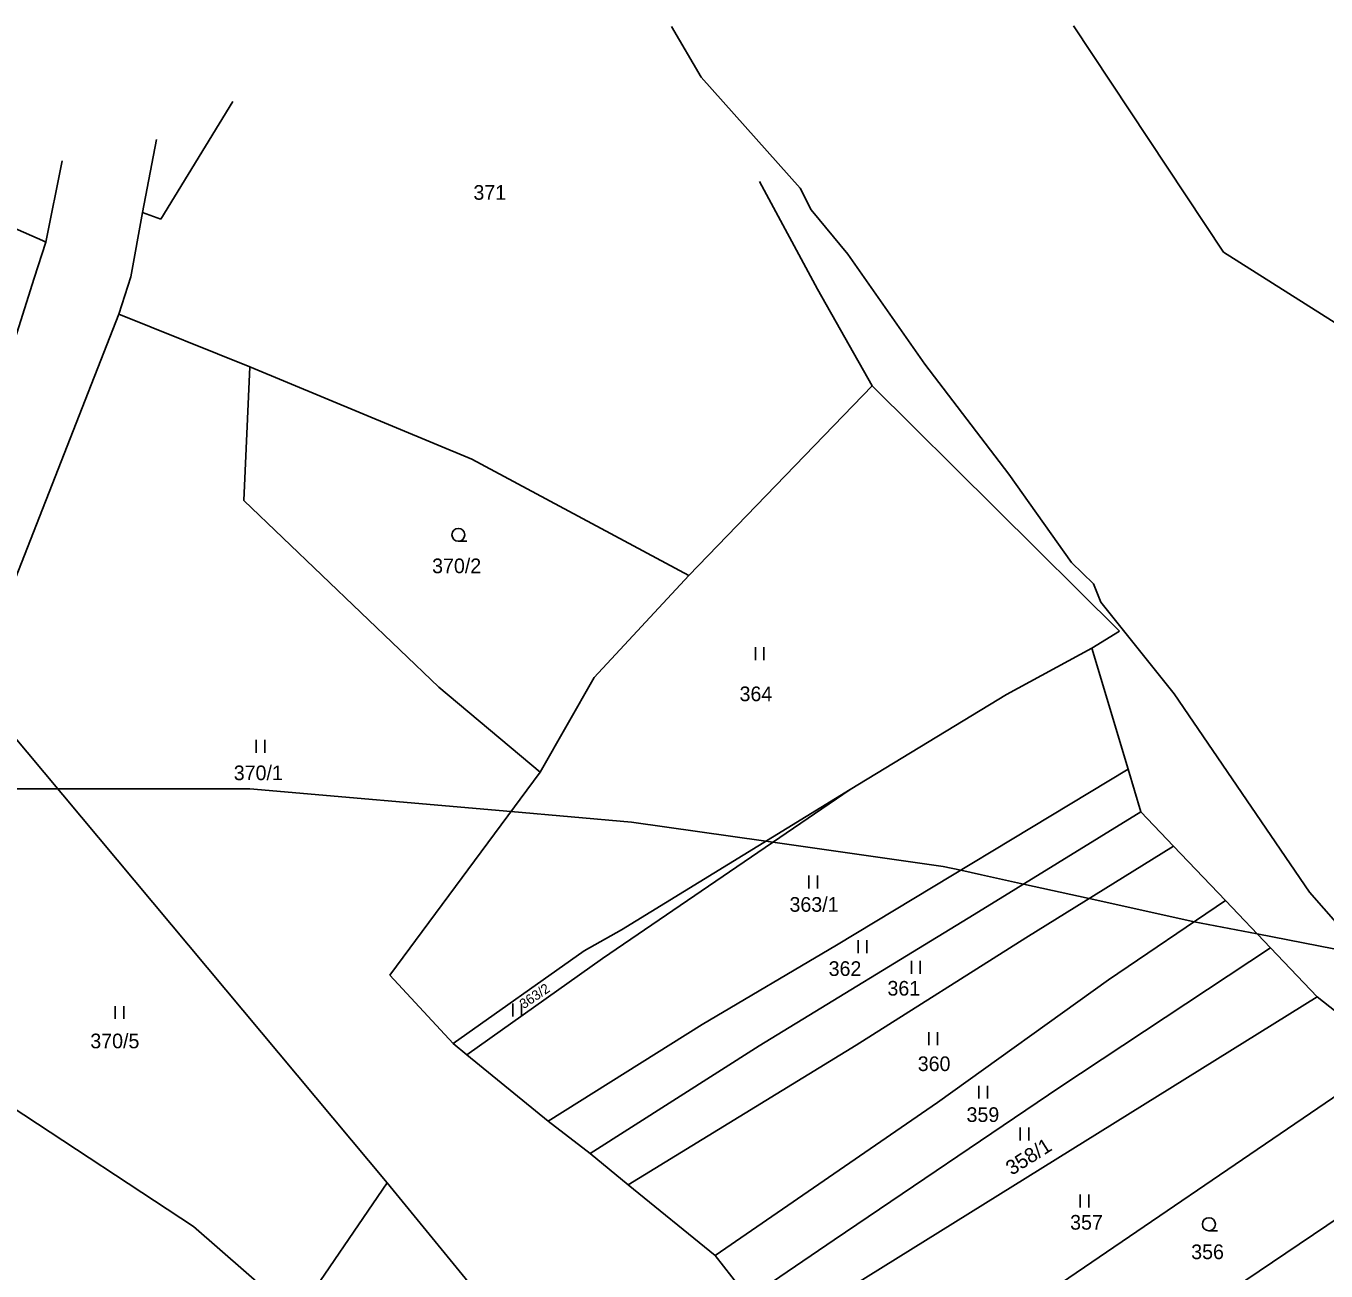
# Model space of a CAD drawing. Extents: x -749173 to -746119, y -1132678 to -1130338.
# Drawn here: x -747979.1 to -747828.3, y -1130840.9 to -1130696.6 of the extents above; entities that cross this region are included whole.
import ezdxf

# ---------------------------------------------------------------- set-up
doc = ezdxf.new("R2010")
doc.units = 0
for name, color, linetype in [('Vrstva 1', 7, 'Continuous'), ('Vrstva 18', 7, 'Continuous'), ('Vrstva 25', 7, 'Continuous'), ('Vrstva 52', 7, 'Continuous'), ('Vrstva 6', 7, 'Continuous')]:
    doc.layers.add(name, color=color, linetype=linetype)

msp = doc.modelspace()

# ---------------------------------------------------------------- linework, layer by layer
at = {"layer": 'Vrstva 1'}
for points in [[(-747963.47, -1130718.96), (-747955.1, -1130705.31)], [(-747963.97, -1130709.72), (-747965.59, -1130718.16)], [(-747974.9, -1130712.19), (-747976.8, -1130721.6)], [(-747894.02, -1130714.58), (-747887.33, -1130727.05)], [(-747965.59, -1130718.16), (-747966.92, -1130725.64)], [(-747965.59, -1130718.16), (-747963.47, -1130718.96)], [(-747976.8, -1130721.6), (-747978.13, -1130725.78)], [(-747978.13, -1130725.78), (-747981.47, -1130736.34)], [(-747966.92, -1130725.64), (-747968.32, -1130729.96)], [(-747887.33, -1130727.05), (-747880.96, -1130738.26)], [(-747968.32, -1130729.96), (-747985.28, -1130773.23)], [(-747953.15, -1130736.09), (-747968.32, -1130729.96)], [(-747953.83, -1130751.57), (-747953.15, -1130736.09)], [(-747953.15, -1130736.09), (-747927.4, -1130746.77)], [(-747880.96, -1130738.26), (-747852.28, -1130766.74)], [(-747902.23, -1130760.25), (-747927.4, -1130746.77)], [(-747931.23, -1130773.21), (-747953.83, -1130751.57)], [(-747902.23, -1130760.25), (-747913.2, -1130772.11)], [(-747855.52, -1130768.71), (-747852.28, -1130766.74)], [(-747855.52, -1130768.71), (-747851.3, -1130782.72)], [(-747919.46, -1130783.07), (-747913.2, -1130772.11)], [(-747937.23, -1130830.7), (-747985.28, -1130773.23)], [(-747919.46, -1130783.07), (-747931.23, -1130773.21)], [(-747919.46, -1130783.07), (-747936.92, -1130806.6)], [(-747851.3, -1130782.72), (-747849.81, -1130787.66)], [(-747849.81, -1130787.66), (-747846.02, -1130791.65)], [(-747846.02, -1130791.65), (-747840.01, -1130797.96)], [(-747840.01, -1130797.96), (-747834.77, -1130803.46)], [(-747834.77, -1130803.46), (-747829.36, -1130809.14)], [(-747929.55, -1130814.55), (-747936.92, -1130806.6)], [(-747959.65, -1130835.75), (-748001.98, -1130807.92)], [(-747829.36, -1130809.14), (-747820.55, -1130816.09)], [(-747927.97, -1130815.84), (-747929.55, -1130814.55)], [(-747918.56, -1130823.54), (-747927.97, -1130815.84)], [(-747867.74, -1130848.23), (-747820.55, -1130816.09)], [(-747913.69, -1130827.28), (-747918.56, -1130823.54)], [(-747812.81, -1130825.22), (-747848.46, -1130849.27)], [(-747909.27, -1130830.92), (-747913.69, -1130827.28)], [(-747937.23, -1130830.7), (-747947.78, -1130846.14)], [(-747937.23, -1130830.7), (-747921.89, -1130849.4)], [(-747899.19, -1130839.1), (-747909.27, -1130830.92)], [(-747947.78, -1130846.14), (-747959.65, -1130835.75)], [(-747895.31, -1130844.05), (-747899.19, -1130839.1)]]:
    msp.add_lwpolyline(points, dxfattribs=at)
at = {"layer": 'Vrstva 25'}
for p, q in [((-747928.96, -1130756.3), (-747927.96, -1130756.3)), ((-747894.52, -1130768.57), (-747894.52, -1130770.07)), ((-747893.52, -1130770.07), (-747893.52, -1130768.57)), ((-747952.4, -1130779.34), (-747952.4, -1130780.84)), ((-747951.4, -1130780.84), (-747951.4, -1130779.34)), ((-747888.32, -1130795.05), (-747888.32, -1130796.55)), ((-747887.32, -1130796.55), (-747887.32, -1130795.05)), ((-747882.58, -1130802.56), (-747882.58, -1130804.06)), ((-747881.58, -1130804.06), (-747881.58, -1130802.56)), ((-747876.42, -1130804.95), (-747876.42, -1130806.45)), ((-747875.42, -1130806.45), (-747875.42, -1130804.95)), ((-747968.75, -1130810.19), (-747968.75, -1130811.69)), ((-747967.75, -1130811.69), (-747967.75, -1130810.19)), ((-747922.63, -1130809.91), (-747922.63, -1130811.41)), ((-747921.63, -1130811.41), (-747921.63, -1130809.91)), ((-747874.39, -1130813.23), (-747874.39, -1130814.73)), ((-747873.39, -1130814.73), (-747873.39, -1130813.23)), ((-747868.6, -1130819.43), (-747868.6, -1130820.93)), ((-747867.6, -1130820.93), (-747867.6, -1130819.43)), ((-747863.8, -1130824.27), (-747863.8, -1130825.77)), ((-747862.8, -1130825.77), (-747862.8, -1130824.27)), ((-747856.85, -1130832.04), (-747856.85, -1130833.54)), ((-747855.85, -1130833.54), (-747855.85, -1130832.04)), ((-747841.93, -1130836.24), (-747840.93, -1130836.24))]:
    msp.add_line(p, q, dxfattribs=at)
for centre in [(-747928.96, -1130755.55), (-747841.93, -1130835.49)]:
    msp.add_circle(centre, 0.75, dxfattribs=at)
at = {"layer": 'Vrstva 52'}
for points in [[(-747823.87, -1130804.25), (-747830.25, -1130797), (-747845.94, -1130774), (-747854.44, -1130763.37), (-747855.31, -1130761.25), (-747857.87, -1130758.75), (-747865.12, -1130748.5), (-747874.87, -1130735.75), (-747883.81, -1130723), (-747888.06, -1130717.87), (-747889.31, -1130715.37), (-747900.81, -1130702.5), (-747904.25, -1130696.62)], [(-747823.87, -1130804.25), (-747836.32, -1130801.83), (-747843.63, -1130800.41), (-747843.81, -1130800.37), (-747855.82, -1130797.73), (-747863.42, -1130796.05), (-747868.29, -1130794.98), (-747870.71, -1130794.45), (-747872.75, -1130794), (-747892.5, -1130791.2), (-747893.31, -1130791.08), (-747908.87, -1130788.87), (-747922.86, -1130787.65), (-747953.12, -1130785), (-747965.94, -1130785), (-747967.99, -1130785), (-747975.44, -1130785), (-747991.67, -1130785)]]:
    msp.add_lwpolyline(points, dxfattribs=at)
at = {"layer": 'Vrstva 6'}
for points in [[(-747857.62, -1130696.55), (-747840.23, -1130722.79)], [(-748009.08, -1130707.45), (-747977.16, -1130721.44)], [(-747977.16, -1130721.44), (-747976.8, -1130721.6)], [(-747840.23, -1130722.79), (-747823.18, -1130733.56)], [(-747902.23, -1130760.25), (-747880.96, -1130738.26)], [(-747865.41, -1130774.06), (-747855.52, -1130768.71)], [(-747883.52, -1130785.07), (-747865.41, -1130774.06)], [(-747885.1, -1130803.15), (-747851.3, -1130782.72)], [(-747912.25, -1130804.68), (-747883.52, -1130785.07)], [(-747883.52, -1130785.07), (-747910.03, -1130801.35)], [(-747869.15, -1130799.59), (-747849.81, -1130787.66)], [(-747863.17, -1130802.29), (-747846.02, -1130791.65)], [(-747853.58, -1130807.15), (-747840.01, -1130797.96)], [(-747894.06, -1130814.79), (-747869.15, -1130799.59)], [(-747910.03, -1130801.35), (-747914.38, -1130803.79)], [(-747900.68, -1130812.35), (-747885.1, -1130803.15)], [(-747882.81, -1130814.71), (-747863.17, -1130802.29)], [(-747914.38, -1130803.79), (-747929.55, -1130814.55)], [(-747927.97, -1130815.84), (-747912.25, -1130804.68)], [(-747859.22, -1130819.6), (-747834.77, -1130803.46)], [(-747873.39, -1130821.38), (-747853.58, -1130807.15)], [(-747883.17, -1130842.59), (-747829.36, -1130809.14)], [(-747918.56, -1130823.54), (-747900.68, -1130812.35)], [(-747913.69, -1130827.28), (-747894.06, -1130814.79)], [(-747909.27, -1130830.92), (-747882.81, -1130814.71)], [(-747885.37, -1130837.32), (-747859.22, -1130819.6)], [(-747899.19, -1130839.1), (-747873.39, -1130821.38)], [(-747895.31, -1130844.05), (-747885.37, -1130837.32)]]:
    msp.add_lwpolyline(points, dxfattribs=at)

# ---------------------------------------------------------------- texts
at = {"layer": 'Vrstva 18'}
for s, p in [('371', (-747927.21, -1130716.7)), ('370/2', (-747932, -1130760)), ('364', (-747896.35, -1130774.84)), ('370/1', (-747955, -1130784)), ('363/1', (-747890.56, -1130799.26)), ('362', (-747886.02, -1130806.7)), ('361', (-747879.2, -1130808.98)), ('370/5', (-747971.63, -1130815.09)), ('360', (-747875.69, -1130817.73)), ('359', (-747870.03, -1130823.63)), ('357', (-747858.02, -1130836.12)), ('356', (-747843.98, -1130839.54))]:
    msp.add_text(s, height=1.7, dxfattribs=at).set_placement(p)
for s, height, rotation, p in [('363/2', 1.14, 34.061, (-747921.38, -1130810.57)), ('358/1', 1.7, 32.3555, (-747864.79, -1130829.88))]:
    msp.add_text(s, height=height, rotation=rotation, dxfattribs=at).set_placement(p)

doc.saveas('drawing.dxf')
